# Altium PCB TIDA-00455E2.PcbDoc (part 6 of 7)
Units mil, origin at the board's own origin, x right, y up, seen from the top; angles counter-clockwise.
Board outline 6693 x 6693.1 mil, 8 copper layers (Layer 1 - Top Layer, Layer 2 - GND, Layer 3 - Sensitive, Layer 4 - GND, Layer 5 - PWR, Layer 6 - Signal, Layer 7 - GND, Layer 8 - Bottom Layer), stack 63.122 mil thick; 537 components, 407 nets, 1686 pads, 1249 vias.
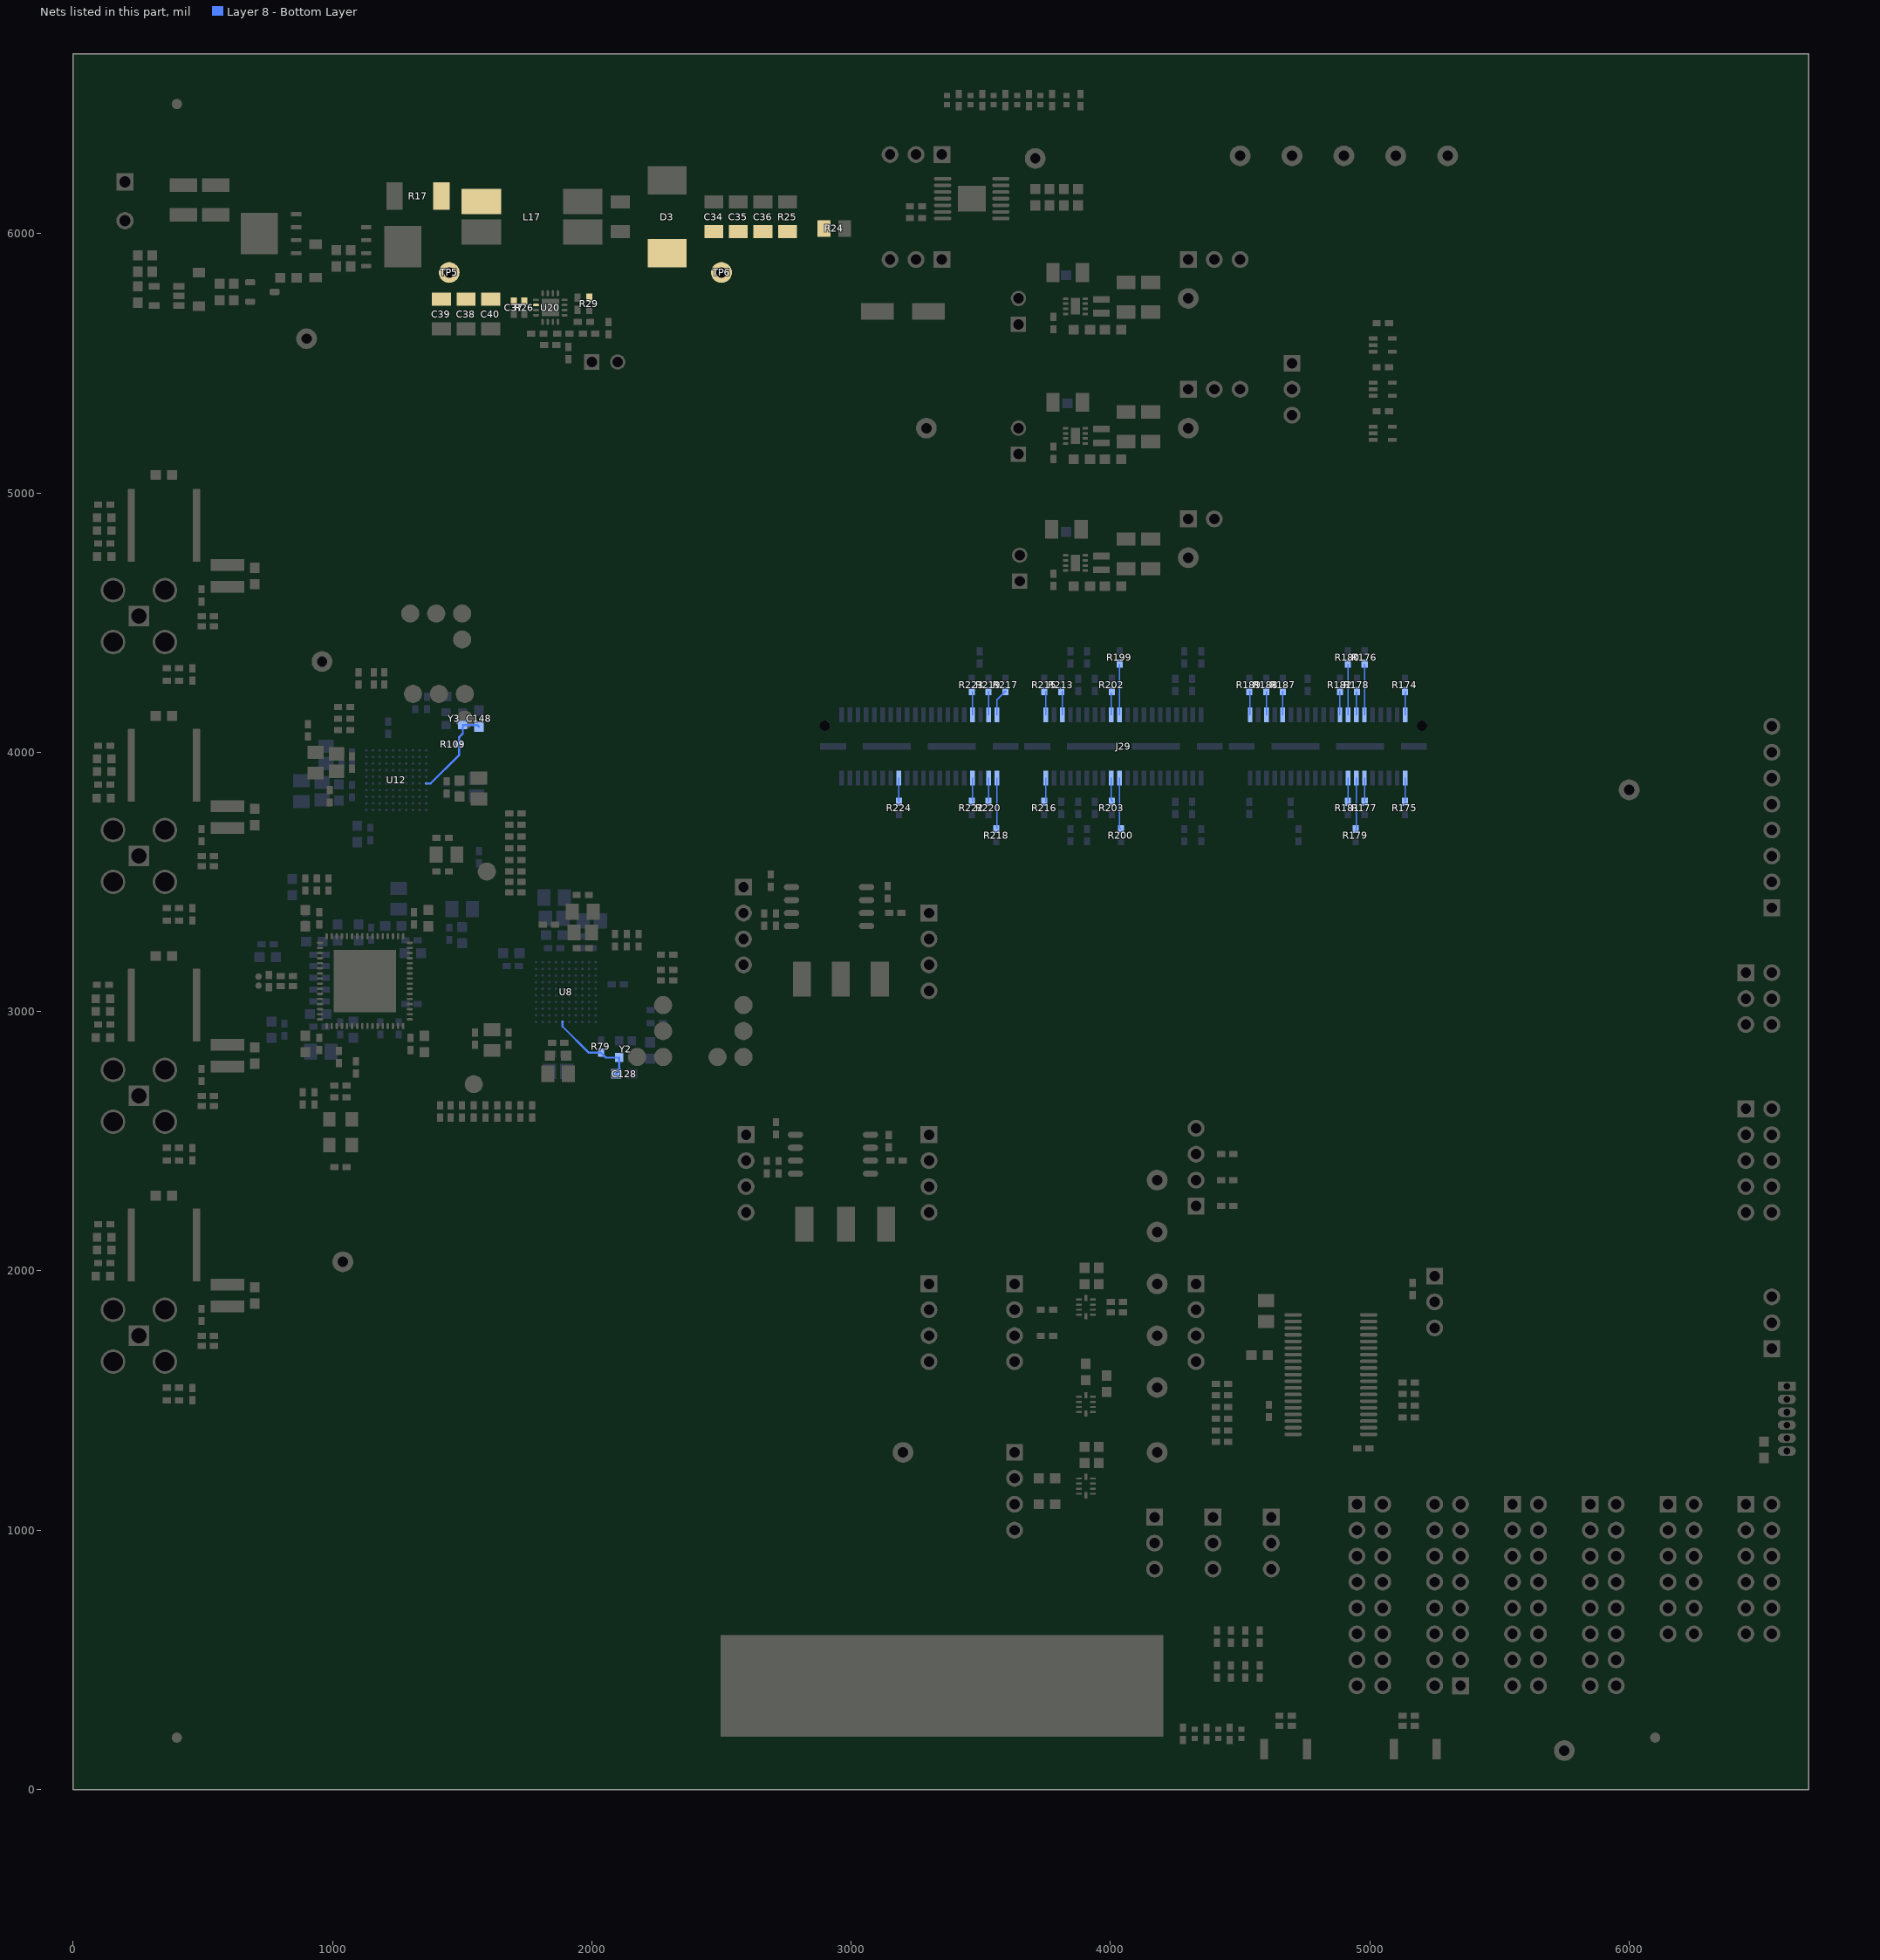
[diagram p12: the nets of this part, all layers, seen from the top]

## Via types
v1: diameter 20, hole 10, Layer 1 - Top Layer to Layer 8 - Bottom Layer, tented both sides, 1063 vias
v2: diameter 12, hole 6, Layer 1 - Top Layer to Layer 8 - Bottom Layer, tented bottom, 140 vias
v3: diameter 19.68, hole 7.87, Layer 1 - Top Layer to Layer 8 - Bottom Layer, 38 vias
v4: diameter 19.68, hole 7.87, Layer 1 - Top Layer to Layer 8 - Bottom Layer, tented top, 4 vias
v5: diameter 15.75, hole 7.87, Layer 1 - Top Layer to Layer 8 - Bottom Layer, 4 vias

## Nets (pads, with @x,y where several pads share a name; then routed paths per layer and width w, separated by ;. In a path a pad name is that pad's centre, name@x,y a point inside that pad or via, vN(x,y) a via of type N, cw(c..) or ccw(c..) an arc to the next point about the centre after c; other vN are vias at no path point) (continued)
VIN1A_HSYNC_0: J29.1 R174.2 | length 90.8
  Layer 8 - Bottom Layer w5: J29.1@5136.8,4143.8 R174.2@5136.8,4234.58
VIN1A_VSYNC_0: J29.2 R175.1 | length 93
  Layer 8 - Bottom Layer w5: R175.1@5135,3808.62 5136.8,3810.42 J29.2@5136.8,3900.89
VIN1B_CLK1: J29.75 R213.2 | length 92.6
  Layer 8 - Bottom Layer w5: J29.75@3813.97,4143.8 R213.2@3813.97,4236.38
VIN2A_CLK: J29.61 R199.2 | length 197
  Layer 8 - Bottom Layer w5: J29.61@4034.44,4143.8 R199.2@4034.44,4340.82
VIN2A_D00: J29.79 R215.2 | length 92.6
  Layer 8 - Bottom Layer w5: J29.79@3750.97,4143.8 R215.2@3750.97,4236.38
VIN2A_D01: J29.80 R216.1 | length 91.3
  Layer 8 - Bottom Layer w5: R216.1@3750.97,3809.6 J29.80@3750.97,3900.89
VIN2A_D02: J29.81 R217.2 | length 114.2
  Layer 8 - Bottom Layer w5: J29.81@3562,4143.8 3562,4202 R217.2@3595.69,4235.69 ; R217.2@3590,4233 3590,4236.38 R217.2@3595,4236.38
VIN2A_D03: J29.82 R218.1 | length 195.3
  Layer 8 - Bottom Layer w5: R218.1@3562,3705.62 J29.82@3562,3900.89
VIN2A_D04: J29.83 R219.2 | length 92.6
  Layer 8 - Bottom Layer w5: J29.83@3530.5,4143.8 R219.2@3530.5,4236.38
VIN2A_D05: J29.84 R220.1 | length 91.8
  Layer 8 - Bottom Layer w5: R220.1@3530.5,3809.12 J29.84@3530.5,3900.89
VIN2A_D06: J29.87 R223.2 | length 90.1
  Layer 8 - Bottom Layer w5: J29.87@3467.51,4143.8 R223.2@3467.51,4233.89
VIN2A_D07: J29.88 R222.1 | length 89.8
  Layer 8 - Bottom Layer w5: R222.1@3467.51,3811.13 J29.88@3467.51,3900.89
VIN2A_DE0: J29.63 R202.2 | length 85.5
  Layer 8 - Bottom Layer w5: J29.63@4002.94,4143.8 R202.2@4002.94,4229.32
VIN2A_HSYNC_0: J29.62 R200.1 | length 199.6
  Layer 8 - Bottom Layer w5: J29.62@4034.44,3900.89 4034.44,3709.18 R200.1@4040,3703.62
VIN2A_VSYNC_0: J29.64 R203.1 | length 93.8
  Layer 8 - Bottom Layer w5: J29.64@4002.94,3900.89 4002.94,3817.06 R203.1@4010,3810
VIN6A_CLK: J29.106 R224.1 | length 92.3
  Layer 8 - Bottom Layer w5: R224.1@3184.04,3808.62 J29.106@3184.04,3900.89
VIN6A_D00: J29.13 R178.2 | length 90.4
  Layer 8 - Bottom Layer w5: J29.13@4947.82,4143.8 R178.2@4947.82,4234.2
VIN6A_D01: J29.14 R179.1 | length 198.4
  Layer 8 - Bottom Layer w5: R179.1@4945,3703.62 4947.82,3706.45 J29.14@4947.82,3900.89
VIN6A_D02: J29.15 R180.2 | length 196.2
  Layer 8 - Bottom Layer w5: J29.15@4916.33,4143.8 R180.2@4916.33,4340.05
VIN6A_D03: J29.16 R181.1 | length 92.8
  Layer 8 - Bottom Layer w5: R181.1@4915,3808.62 4916.33,3809.95 J29.16@4916.33,3900.89
VIN6A_D04: J29.35 R188.2 | length 91.2
  Layer 8 - Bottom Layer w5: J29.35@4601.37,4143.8 R188.2@4601.37,4235.01
VIN6A_D05: J29.39 R189.1 | length 94
  Layer 8 - Bottom Layer w5: R189.1@4535,4236.38 4538.38,4233 J29.39@4538.38,4143.8
VIN6A_D06: J29.31 R187.2 | length 92.6
  Layer 8 - Bottom Layer w5: J29.31@4664.36,4143.8 R187.2@4664.36,4236.38
VIN6A_D07: J29.17 R182.2 | length 92.6
  Layer 8 - Bottom Layer w5: J29.17@4884.83,4143.8 4884.83,4236.21 R182.2@4885,4236.38
VIN6A_HSYNC_0: J29.11 R176.2 | length 196.9
  Layer 8 - Bottom Layer w5: J29.11@4979.32,4143.8 R176.2@4979.32,4340.7
VIN6A_VSYNC_0: J29.12 R177.1 | length 92.5
  Layer 8 - Bottom Layer w5: J29.12@4979.32,3900.89 4979.32,3809.3 R177.1@4980,3808.62
VIN_PROTECT: C37.1 C38.1 C39.1 C40.1 L17.1 R17.2 R26.1 TP5.1 U20.2
VOUT: C34.1 C35.1 C36.1 D3.1 R24.1 R25.2 R29.1 TP6.1
XTAL_OUT_OV1: C128.1 R79.2 U8.F1 Y2.3 | length 352.5
  Layer 8 - Bottom Layer w8: U8.F1@1887.2,2959.84 1887.2,2942.8 1988.62,2841.38 R79.2@2035,2841.38 2053.86,2822.52 Y2.3@2105.39,2822.52 2105.39,2771.89 C128.1@2093.5,2760
XTAL_OUT_OV2: C148.1 R109.2 U12.F1 Y3.3 | length 359.5
  Layer 8 - Bottom Layer w8: U12.F1@1361.4,3879.7 1378.44,3879.7 1488.62,3989.88 R109.2@1488.62,4030 1488.62,4058.62 1502.48,4072.48 Y3.3@1502.48,4105.39 1558.11,4105.39 C148.1@1565,4098.5
pads on no net: FID1.1 FID2.1 FID3.1 FID4.1 FID5.1 FID6.1 J23.1 J23.6 J25.4 J25.6 J29.3 J29.4 J29.5 J29.6 J29.7 J29.8 J29.9 J29.10 J29.18 J29.19 J29.20 J29.21 J29.22 J29.23 J29.24 J29.29 J29.33 J29.36 J29.37 J29.38 J29.86 J29.99 J29.100 J29.101 J29.102 J29.103 J29.104 J29.105 J29.107 J29.108 J29.109 J29.110 J29.111 J29.112 J29.113 J29.114 J29.117 J29.118 J29.119 J29.120 J29.MH1 J29.MH2 J32.2 Logo1.0 R52.2 U2.1 U2.2 U4.1 U4.4 U4.11 U8.B7 U8.B8 U8.B10 U8.C7 U8.E7 U8.F3 U8.F7 U8.H2 U8.J9 U8.J10 U8.K6 U12.B7 U12.B8 U12.B10 U12.C7 U12.E7 U12.F3 U12.F7 U12.H2 U12.J9 U12.J10 U12.K6 U18.1 U18.2 U19.1 U19.2

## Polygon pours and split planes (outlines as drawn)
GND on Layer 2 - GND "Layer 2 - GND- GND" (solid, remove dead copper, pour order 6): 20,20 6670,20 6670,6670 20,6670
GND on Layer 7 - GND "Layer 5 - GND- GND" (solid, remove dead copper, pour order 7): 20,20 6670,20 6670,6670 20,6670
1V8 on Layer 5 - PWR "Layer 3 - PWR- 1V8" (solid, remove dead copper, pour order 9): 4440,5400 4440,5220 4360,5140 4140,4920 2010,4920 1960,4870 1960,4580 1880,4500 900,4500 800,4400 800,4040 1110,3730 1250,3730 1300,3730 1410,3620 1410,3540 1460,3490 1550,3490 1636,3576 1636,3666 1605,3697 1605,3840 1670,3840 1690,3820 1690,3500 1720,3470 1780,3470 1785,3465 1785,3415 1780,3410 1745,3410 1730,3395 1730,3300 1730,3025 1660,2955 1380,2955 1345,2920 1345,2725 1380,2690 1660,2690 1680,2710 1730,2710 1850,2710 1850,2630 1810,2590 1355,2590 1320,2555 1320,2400 1320,2170 1290,2140 660,2140 470,2330 470,5070 850,5450 3690,5450 3840,5600 4360,5600 4440,5520
3V3 on Layer 5 - PWR "Layer 3 - PWR- 3V3" (solid, remove dead copper, pour order 10): 4360,5950 4340,5970 3510,5970 3462.5,5970 3445.62,5970 3310.62,6105 3220,6105 3205.62,6119.37 3205.63,6150.63 3220,6165 3340,6165 3470,6035 3955,6035 4000,6080 4450,6080 6225,6080 6370,5935 6402.5,5902.5 6402.5,3347.5 6370,3315 6370,1670 6490,1550 6490,1245 6370,1125 6370,270 1530,270 1425,375 1425,1615 1465,1655 2150,1655 2465,1970 2465,2545 2500,2580 2590,2670 4880,2670 5010,2800 5010,3530 5060,3580 5510,3580 5670,3740 5670,4870 5490,5050 5370,5050 5300,4980 5300,4790 5480,4610 5480,3850 5400,3770 4920,3770 4810,3660 4810,2900 4750,2840 2490,2840 2300,2650 2300,2200 2240,2140 1390,2140 1360,2170 1360,2530 1390,2560 1465,2560 1474,2551 1474,2536 1486,2524 1564,2524 1575,2535 1575,2550 1585,2560 1645,2560 1654,2551 1654,2536 1666,2524 1784,2524 1820,2560 1880,2620 1880,2760 1829.01,2810.99 1746,2811 1725,2790 1590,2790 1559,2821 1464,2821 1425,2860 1410,2875 1395,2875 1380,2890 1380,2910 1395,2925 1515,2925 1675,2925 1680,2930 1690,2940 1935,2940 1960,2915 2035,2915 2145,3025 2200,3025 2240,3065 2240,3120 2240,3350 2110,3480 1810,3480 1800,3490 1740,3490 1720,3510 1720,3830 1680,3870 1610,3870 1600,3870 1595,3870 1535,3810 1510,3785 1510,3755 1569,3696 1569,3609 1540,3580 1514,3554 1514,3534 1504,3524 1486,3524 1450,3560 1450,3640 1380,3710 1380,3940 1400,3960 1400,4035 1380,4055 1380,4190 1310,4260 1000,4260 960,4220 960,4130 940,4110 870,4110 850,4130 850,4380 930,4460 1900,4460 2010,4570 4370,4570 4570,4770 4570,5520 4360,5730
GND on Layer 4 - GND "Layer 4 - GND- GND" (solid, remove dead copper, pour order 8): 20,20 6670,20 6670,6670 20,6670

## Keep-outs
Keep-Out Layer:
  text ".Layer_Name" at 577,-858.49 h60

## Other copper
Layer 1 - Top Layer:
  region net 3V3: 4395,460 4590,460 4590,585 4395,585
  region net GND: 6640,125 6290,125 6290,425 6640,425
  region net GND: 1915,50 1915,400 2215,400 2215,50
  region net GND: 50,1225 400,1225 400,925 50,925
  region net GND: 5030,5247 5043,5260 5043,5370 5030,5383 4963,5383 4935,5355 4935,5275 4963,5247
  region net GND: 5030,5417 5043,5430 5043,5540 5030,5553 4963,5553 4935,5525 4935,5445 4963,5417
  region net NetJ6_2: 3270,6335 3290,6315 3290,6265 3310,6245 3382,6245 3390,6237 3390,6156 3382,6148 3317,6148 3252,6148 3210,6190 3210,6315 3230,6335
  region net LOCAL_3V3: 3892,5715 4000,5715 4030,5745 4200,5745 4245,5790 4245,5930 4255,5940 4335,5940 4355,5920 4355,5695 4270,5610 4020,5610 4020,5650 3995,5675 3935,5675 3925,5685 3925,5695 3915,5705 3892,5705
  region net GND: 4195,5785 4195,5870 4175,5890 3815,5890 3815,5744 3843,5744 3848,5739 3848,5700 3844,5696 3817,5696 3805,5684 3805,5656 3796,5647 3768,5647 3768,5582 3780,5570 3871,5570 3883,5582 3883,5793 3900,5810 3930,5810 3955,5785
  region net LOCAL_1V8: 3892,5215 4000,5215 4030,5245 4200,5245 4245,5290 4245,5420 4265,5440 4335,5440 4355,5420 4355,5195 4270,5110 4020,5110 4020,5150 3995,5175 3935,5175 3925,5185 3925,5195 3915,5205 3892,5205
  region net GND: 4195,5285 4195,5370 4175,5390 3815,5390 3815,5244 3843,5244 3848,5239 3848,5200 3844,5196 3817,5196 3805,5184 3805,5156 3796,5147 3768,5147 3768,5082 3780,5070 3871,5070 3883,5082 3883,5293 3900,5310 3930,5310 3955,5285
  region net GND: 4195,4795 4195,4880 4175,4900 3815,4900 3815,4754 3843,4754 3848,4749 3848,4710 3844,4706 3817,4706 3805,4694 3805,4666 3796,4657 3768,4657 3768,4592 3780,4580 3871,4580 3883,4592 3883,4803 3900,4820 3930,4820 3955,4795
  region net LOCAL_1V1: 3892,4725 4000,4725 4030,4755 4200,4755 4245,4800 4245,4930 4265,4950 4335,4950 4355,4930 4355,4705 4270,4620 4020,4620 4020,4660 3995,4685 3935,4685 3925,4695 3925,4705 3915,4715 3892,4715
  region net 3V3: 1450,3642.5 1536.24,3642.5 1536.24,3572.5 1450,3572.5
  region net GND: 1041.24,4057.5 1053.24,4057.5 1041.24,4069.5 1041.24,4102.5 1041.24,4217.5 986.24,4217.5 976.24,4207.5 976.24,4057.5
  region net GND: 1091.24,3962.5 1091.24,4047.5 1081.24,4057.5 976.24,4057.5 976.24,4042.5 986.24,4032.5 986.24,3962.5
  region net GND: 1421.24,3857.5 1511.24,3857.5 1511.24,3772.5 1431.24,3772.5 1421.24,3782.5
  region net 1V8: 1526.24,3847.5 1631.24,3847.5 1631.24,3787.5 1531.24,3787.5 1526.24,3792.5
  region net GND: 20,20 6670,20 6670,6670 20,6670 20,50 50,50 50,6640 6640,6640 6640,1590 6655,1590 6655,1270 6640,1270 6640,50 20,50
  region net GND: 2065,3280 2065,3268 2077,3280 2110,3280 2225,3280 2225,3335 2215,3345 2065,3345
  region net GND: 1970,3230 2055,3230 2065,3240 2065,3345 2050,3345 2040,3335 1970,3335
  region net NetC1_1: 340,5090 340,4755 320,4735 125,4735 125,4875 195,4875 210,4890 210,5070 230,5090
  region net NetL3_2: 360,5090 665,5090 720,5035 720,4690 425,4690 360,4755
  region net NetL3_1: 480,4610 705,4610 720,4625 720,4670 495,4670 480,4655
  region net NetL5_1: 480,3685 705,3685 720,3700 720,3745 495,3745 480,3730
  region net NetL5_2: 360,4160 665,4160 720,4105 720,3760 425,3760 360,3825
  region net NetC5_1: 340,4160 340,3825 320,3805 125,3805 125,3945 195,3945 210,3960 210,4140 230,4160
  region net NetL11_1: 480,2760 705,2760 720,2775 720,2820 495,2820 480,2805
  region net NetL11_2: 360,3240 665,3240 680,3225 680,3055 720,3015 720,2840 690,2840 425,2840 360,2905
  region net NetC15_1: 340,3235 340,2900 320,2880 125,2880 125,3020 195,3020 210,3035 210,3215 230,3235
  region net NetL13_1: 480,1835 705,1835 720,1850 720,1895 495,1895 480,1880
  region net NetL13_2: 360,2315 665,2315 720,2260 720,1915 425,1915 360,1980
  region net NetC19_1: 340,2315 340,1980 320,1960 125,1960 125,2100 195,2100 210,2115 210,2295 230,2315
  region net 3V3: 1650,2875 1650,2795 1580,2795 1580,2875
  region net 1V8: 1025,2385 945,2385 925,2405 925,2515 1025,2515
  region net GND: 1050,2555 1130,2555 1130,2615 1050,2615
  region net NetC30_2: 160,6090 160,5915 180,5895 780,5895 800,5915 800,6090 780,6110 180,6110
  region net NetR21_1: 230,5875 230,5775 330,5775 340,5785 340,5805 330,5815 280,5815 270,5825 270,5875
  region net NetC32_1: 285,5835 290,5830 340,5830 390,5780 690,5780 710,5800 710,5855 690,5875 285,5875
  region net NetM1_3: 760,5760 750,5770 750,5845 760,5855 815,5855 825,5845 825,5770 815,5760
  region net NetC29_2: 850,5800 840,5810 840,5885 850,5895 1145,5895 1155,5885 1155,5810 1145,5800
  region net NetC29_1: 840,5915 1150,5915 1150,6035 840,6035
  region net GND: 620,6150 160,6150 130,6120 130,5900 155,5875 210,5875 210,5770 225,5755 340,5755 360,5735 360,5710 380,5690 435,5690 455,5710 455,5745 475,5765 720,5765 740,5745 740,5675 720,5655 120,5655 50,5585 50,5725 50,6170 50,6350 140,6260 600,6260 620,6240
  region net NetQ2_5: 1210,5840 1190,5860 1190,6185 1205,6200 1350,6200 1365,6185 1365,5840
  region net VIN_PROTECT: 1375,6185 1390,6200 1635,6200 1650,6185 1650,6075 1495,6075 1475,6055 1475,5955 1495,5935 1735,5935 1755,5915 1755,5745 1770,5730 1797,5730 1797,5720 1375,5720
  region net NetC33_2: 1797,5739 1776,5739 1770,5745 1770,6035 1790,6055 2130,6055 2150,6035 2150,5850 2130,5830 1850,5830 1835,5815 1835,5758 1804,5758 1797,5751
  region net NetC33_1: 1877.5,6075 1857.5,6095 1857.5,6240 1877.5,6260 2362.5,6260 2362.5,6095 2342.5,6075
  region net VOUT: 1975,5735 1975,5790 1995,5810 2140,5810 2175,5845 2175,5970 2175,6035 2195,6055 2920,6055 2920,5755 2900,5735
  region net GND: 1807,5748 1841,5748 1845,5752 1845,5805 1855,5815 1945,5815 1960,5800 1960,5735 1930,5735 1920,5725 1920,5700 1880,5700 1865,5685 1835,5685 1835,5535 1825,5525 1760,5525 1725,5525 1687.5,5562.5 1710,5585 1710,5605 1730,5585 1785,5585 1795,5595 1795,5640 1805,5650 1805,5670 1807,5672
  region net GND: 1495,5955 1720,5955 1720,6055 1495,6055
  region net GND: 1715,5710 1715,5580 1695,5560 1395,5560 1375,5580 1375,5710
  region net GND: 2430,6075 2410,6095 2410,6175 2430,6195 2790,6195 2810,6175 2810,6095 2790,6075
  region net V_CAM: 3540,6150 3895,6150 3895,6320 3875,6340 3560,6340 3540,6320
  region net V_MAIN: 2950,5880 2970,5860 3165,5860 3185,5880 3185,6320 3165,6340 2970,6340 2950,6320
  region net NetC44_1: 3230,5935 3210,5915 3210,4745 3230,4725 3790,4725 3800,4735 3838,4735 3838,4745 3810,4745 3800,4755 3800,4900 3710,4900 3690,4920 3690,5075 3670,5095 3615,5095 3595,5115 3595,5200 3615,5220 3795,5220 3800,5225 3838,5225 3838,5235 3810,5235 3805,5240 3805,5390 3710,5390 3690,5410 3690,5575 3670,5595 3615,5595 3595,5615 3595,5700 3615,5720 3795,5720 3800,5725 3838,5725 3838,5735 3810,5735 3805,5740 3805,5775 3805,5845 3805,5890 3465,5890 3420,5845 3310,5845 3290,5865 3290,5915 3270,5935
  region net NetL18_1: 3892,5725 3990,5725 4000,5735 4000,5760 3930,5760 3925,5755 3925,5745 3915,5735 3892,5735
  region net NetL19_1: 3892,5225 3990,5225 4000,5235 4000,5260 3930,5260 3925,5255 3925,5245 3915,5235 3892,5235
  region net NetL20_1: 3892,4735 3990,4735 4000,4745 4000,4770 3930,4770 3925,4765 3925,4755 3915,4745 3892,4745
  region net GND: 3165,5650 3150,5635 3050,5635 3035,5650 3035,5750 3050,5765 3150,5765 3165,5750
  region net GND: 4775,110 4705,110 4705,200 4775,200
  region net GND: 5075,110 5145,110 5145,200 5075,200
  region net GND: 3899,1147 3913,1147 3915,1145 3965,1145 3975,1135 3975,1105 3965,1095 3909,1095 3899,1105
  region net GND: 3899,1462 3913,1462 3915,1460 3965,1460 3975,1450 3975,1420 3965,1410 3909,1410 3899,1420
  region net GND: 3899,1837 3913,1837 3915,1835 3965,1835 3975,1825 3975,1795 3965,1785 3909,1785 3899,1795
  region net GND: 1865,2900 1865,2810 1780,2810 1780,2890 1790,2900
  region net 1V8: 1855,2795 1855,2690 1795,2690 1795,2790 1800,2795
  region net GND: 50,5575 400,5575 400,5275 50,5275
  region net GND: 5400,6290 5400,6640 5700,6640 5700,6290
  region net GND: 380,2410 380,2505 410,2535 410,2650 335,2650 300,2615 205,2615 190,2630 190,2720 205,2735 300,2735 335,2700 410,2700 410,2815 375,2850 50,2850 50,2410
  region net GND: 380,3335 380,3430 410,3460 410,3575 335,3575 300,3540 205,3540 190,3555 190,3645 205,3660 300,3660 335,3625 410,3625 410,3740 375,3775 50,3775 50,3335
  region net GND: 380,1485 380,1580 410,1610 410,1725 335,1725 300,1690 205,1690 190,1705 190,1795 205,1810 300,1810 335,1775 410,1775 410,1890 375,1925 50,1925 50,1485
  region net GND: 380,4260 380,4355 410,4385 410,4500 335,4500 300,4465 205,4465 190,4480 190,4570 205,4585 300,4585 335,4550 410,4550 410,4665 375,4700 50,4700 50,4260
  text ".Layer_Name" at 577,-858.49 h60
Layer 2 - GND:
  pour cut-out: 1827.5,3226.24 1827.5,3156.24 1792.5,3156.24 1792.5,3176.24 1747.5,3176.24 1747.5,3101.24 1775.5,3101.24 1775.5,2951.24 1847.5,2951.24 1847.5,2891.24 1902.5,2891.24 1902.5,2951.24 1952.5,2951.24 1952.5,2925.24 2024.5,2925.24 2024.5,2950.24 2052.5,2950.24 2052.5,3096.24 2035.76,3096.24 2024.5,3107.5 2024.5,3132 2024.5,3201.24 1897.5,3201.24 1897.5,3226.24
  pour cut-out: 1095,3820 1165,3820 1165,3785 1145,3785 1145,3740 1220,3740 1220,3768 1370,3768 1370,3840 1430,3840 1430,3895 1370,3895 1370,3945 1396,3945 1396,4017 1371,4017 1371,4045 1240,4045 1212,4017 1195,4017 1120,4017 1120,3890 1095,3890
  region net GND: 2025,3120 1976,3120 1961,3105 1950,3105 1942,3113 1942,3130 1945,3133 2025,3133
  pour cut-out: 1040,4440 1040,4400 1070,4370 1070,4340 1090,4320 1257,4320 1290,4353 1290,4410 1260,4440
  pour cut-out: 2325,3230 2345,3250 2420,3250 2440,3230 2440,3180 2450,3170 2450,3135 2495,3090 2495,3070 2475,3050 2455,3050 2415,3090 2345,3090 2325,3110
  pour cut-out: 4900,345 5100,345 5100,1150 4900,1150
  pour cut-out: 5200,345 5400,345 5400,1150 5200,1150
  pour cut-out: 5500,345 5700,345 5700,1150 5500,1150
  pour cut-out: 6100,550 6300,550 6300,1150 6100,1150
  pour cut-out: 6400,550 6600,550 6600,1150 6400,1150
  pour cut-out: 5900,1150 6000,1150 6000,350 5900,350
  pour cut-out: 6500,1645 6600,1645 6600,1950 6500,1950
  pour cut-out: 6400,2175 6500,2175 6500,2275 6600,2275 6600,2575 6500,2575 6500,2675 6400,2675
  pour cut-out: 6400,2900 6600,2900 6600,3200 6400,3200
  pour cut-out: 6500,3350 6600,3350 6600,4050 6500,4050
  pour cut-out: 4380,2505 4280,2505 4280,2200 4380,2200
  pour cut-out: 4380,2005 4280,2005 4280,1700 4380,1700
  pour cut-out: 3680,2005 3580,2005 3580,1700 3680,1700
  pour cut-out: 3350,2005 3250,2005 3250,1700 3350,1700
  pour cut-out: 3350,2580 3250,2580 3250,2275 3350,2275
  pour cut-out: 2645,2580 2545,2580 2545,2275 2645,2275
  pour cut-out: 2635,3535 2535,3535 2535,3230 2635,3230
  pour cut-out: 3350,3435 3250,3435 3250,3130 3350,3130
  pour cut-out: 3405,6255 3405,6355 3100,6355 3100,6255
  pour cut-out: 3405,5850 3405,5950 3100,5950 3100,5850
  pour cut-out: 4555,5850 4555,5950 4250,5950 4250,5850
  pour cut-out: 4555,5350 4555,5450 4250,5450 4250,5350
  pour cut-out: 4750,5555 4650,5555 4650,5250 4750,5250
  pour cut-out: 3680,1355 3580,1355 3580,1050 3680,1050
  pour cut-out: 1950,5455 2150,5455 2150,5555 1950,5555
  pour cut-out: 3695,5600 3695,5800 3595,5800 3595,5600
  pour cut-out: 3695,5100 3695,5300 3595,5300 3595,5100
  pour cut-out: 3700,4610 3700,4810 3600,4810 3600,4610
  pour cut-out: 4250,4850 4450,4850 4450,4950 4250,4950
  pour cut-out: 5200,2030 5200,1830 5300,1830 5300,2030
  pour cut-out: 4570,1100 4570,900 4670,900 4670,1100
  pour cut-out: 4345,1100 4345,900 4445,900 4445,1100
  pour cut-out: 4120,1100 4120,900 4220,900 4220,1100
  region net GND: 1201.24,4017.5 1201.24,3968.5 1216.24,3953.5 1216.24,3942.5 1208.24,3934.5 1191.24,3934.5 1188.24,3937.5 1188.24,4017.5
  text ".Layer_Name" at 577,-858.49 h60
Layer 5 - PWR:
  pour cut-out: 3350,3335 3250,3335 3250,3030 3350,3030
  pour cut-out: 2635,3435 2535,3435 2535,3130 2635,3130
  region net 3V3: 6402.5,3347.5 6572.5,3347.5 6590,3365 6590,3435 6575,3450 6450,3450 6395,3505 6395,3355
  pour cut-out: 4900,345 5100,345 5100,1150 4900,1150
  pour cut-out: 5200,345 5400,345 5400,1150 5200,1150
  pour cut-out: 5500,345 5700,345 5700,1150 5500,1150
  pour cut-out: 5800,345 6000,345 6000,1150 5800,1150
  pour cut-out: 6100,545 6300,545 6300,1150 6100,1150
  pour cut-out: 4120,1000 4120,800 4220,800 4220,1000
  pour cut-out: 4345,1000 4345,800 4445,800 4445,1000
  pour cut-out: 4570,1000 4570,800 4670,800 4670,1000
  pour cut-out: 5200,1930 5200,1730 5300,1730 5300,1930
  pour cut-out: 3680,1255 3580,1255 3580,950 3680,950
  pour cut-out: 3350,1905 3250,1905 3250,1600 3350,1600
  pour cut-out: 3680,1905 3580,1905 3580,1600 3680,1600
  pour cut-out: 4380,1905 4280,1905 4280,1600 4380,1600
  pour cut-out: 3350,2480 3250,2480 3250,2175 3350,2175
  pour cut-out: 2645,2480 2545,2480 2545,2175 2645,2175
  pour cut-out: 4750,5555 4650,5555 4650,5250 4750,5250
  pour cut-out: 4380,2605 4280,2605 4280,2200 4380,2200
  text ".Layer_Name" at 577,-858.49 h60
Layer 6 - Signal:
  text ".Layer_Name" at 577,-858.49 h60
Layer 7 - GND:
  pour cut-out: 1095,3820 1165,3820 1165,3785 1145,3785 1145,3740 1220,3740 1220,3768 1370,3768 1370,3840 1430,3840 1430,3895 1370,3895 1370,3945 1396,3945 1396,4017 1371,4017 1371,4045 1240,4045 1212,4017 1195,4017 1120,4017 1120,3890 1095,3890
  pour cut-out: 1827.5,3226.24 1827.5,3156.24 1792.5,3156.24 1792.5,3176.24 1747.5,3176.24 1747.5,3101.24 1775.5,3101.24 1775.5,2951.24 1847.5,2951.24 1847.5,2891.24 1902.5,2891.24 1902.5,2951.24 1952.5,2951.24 1952.5,2925.24 2024.5,2925.24 2024.5,2950.24 2052.5,2950.24 2052.5,3096.24 2035.76,3096.24 2024.5,3107.5 2024.5,3132 2024.5,3201.24 1897.5,3201.24 1897.5,3226.24
  region net GND: 2025,3120 1976,3120 1961,3105 1950,3105 1942,3113 1942,3130 1945,3133 2025,3133
  pour cut-out: 1040,4440 1040,4400 1070,4370 1070,4340 1090,4320 1260,4320 1290,4350 1290,4410 1260,4440
  pour cut-out: 2325,3230 2345,3250 2420,3250 2440,3230 2440,3180 2450,3170 2450,3135 2495,3090 2495,3070 2475,3050 2455,3050 2415,3090 2345,3090 2325,3110
  pour cut-out: 5900,1150 6000,1150 6000,350 5900,350
  pour cut-out: 6400,550 6600,550 6600,1150 6400,1150
  pour cut-out: 6100,550 6300,550 6300,1150 6100,1150
  pour cut-out: 5500,345 5700,345 5700,1150 5500,1150
  pour cut-out: 5200,345 5400,345 5400,1150 5200,1150
  pour cut-out: 4900,345 5100,345 5100,1150 4900,1150
  pour cut-out: 6500,3350 6600,3350 6600,4050 6500,4050
  pour cut-out: 6400,2900 6600,2900 6600,3200 6400,3200
  pour cut-out: 6400,2175 6500,2175 6500,2275 6600,2275 6600,2575 6500,2575 6500,2675 6400,2675
  pour cut-out: 6500,1645 6600,1645 6600,1950 6500,1950
  pour cut-out: 4280,2195 4380,2195 4380,2500 4280,2500
  pour cut-out: 4280,1695 4380,1695 4380,2000 4280,2000
  pour cut-out: 3580,1695 3680,1695 3680,2000 3580,2000
  pour cut-out: 3250,1695 3350,1695 3350,2000 3250,2000
  pour cut-out: 3580,1045 3680,1045 3680,1350 3580,1350
  pour cut-out: 3250,2270 3350,2270 3350,2575 3250,2575
  pour cut-out: 2545,2270 2645,2270 2645,2575 2545,2575
  pour cut-out: 2535,3225 2635,3225 2635,3530 2535,3530
  pour cut-out: 3250,3125 3350,3125 3350,3430 3250,3430
  pour cut-out: 4650,5245 4750,5245 4750,5550 4650,5550
  pour cut-out: 3095,6355 3095,6255 3400,6255 3400,6355
  pour cut-out: 3095,5950 3095,5850 3400,5850 3400,5950
  pour cut-out: 4245,5950 4245,5850 4550,5850 4550,5950
  pour cut-out: 4245,5450 4245,5350 4550,5350 4550,5450
  pour cut-out: 3595,5800 3595,5600 3695,5600 3695,5800
  pour cut-out: 3595,5300 3595,5100 3695,5100 3695,5300
  pour cut-out: 3600,4810 3600,4610 3700,4610 3700,4810
  pour cut-out: 1950,5455 2150,5455 2150,5555 1950,5555
  pour cut-out: 4250,4850 4450,4850 4450,4950 4250,4950
  pour cut-out: 5200,2030 5200,1830 5300,1830 5300,2030
  pour cut-out: 4570,1100 4570,900 4670,900 4670,1100
  pour cut-out: 4345,1100 4345,900 4445,900 4445,1100
  pour cut-out: 4120,1100 4120,900 4220,900 4220,1100
  region net GND: 1201.24,4017.5 1201.24,3968.5 1216.24,3953.5 1216.24,3942.5 1208.24,3934.5 1191.24,3934.5 1188.24,3937.5 1188.24,4017.5
  text ".Layer_Name" at 577,-858.49 h60
Layer 3 - Sensitive:
  text ".Layer_Name" at 577,-858.49 h60
Layer 4 - GND:
  pour cut-out: 1827.5,3226.24 1827.5,3156.24 1792.5,3156.24 1792.5,3176.24 1747.5,3176.24 1747.5,3101.24 1775.5,3101.24 1775.5,2951.24 1847.5,2951.24 1847.5,2891.24 1902.5,2891.24 1902.5,2951.24 1952.5,2951.24 1952.5,2925.24 2024.5,2925.24 2024.5,2950.24 2052.5,2950.24 2052.5,3096.24 2035.76,3096.24 2024.5,3107.5 2024.5,3132 2024.5,3201.24 1897.5,3201.24 1897.5,3226.24
  pour cut-out: 1095,3820 1165,3820 1165,3785 1145,3785 1145,3740 1220,3740 1220,3768 1370,3768 1370,3840 1430,3840 1430,3895 1370,3895 1370,3945 1396,3945 1396,4017 1371,4017 1371,4045 1240,4045 1212,4017 1195,4017 1120,4017 1120,3890 1095,3890
  region net GND: 2025,3120 1976,3120 1961,3105 1950,3105 1942,3113 1942,3130 1945,3133 2025,3133
  pour cut-out: 1040,4440 1040,4400 1070,4370 1070,4340 1090,4320 1263,4320 1290,4347 1290,4410 1260,4440
  pour cut-out: 2325,3230 2345,3250 2420,3250 2440,3230 2440,3180 2450,3170 2450,3135 2495,3090 2495,3070 2475,3050 2455,3050 2415,3090 2345,3090 2325,3110
  pour cut-out: 5900,1150 6000,1150 6000,350 5900,350
  pour cut-out: 6400,550 6600,550 6600,1150 6400,1150
  pour cut-out: 6100,550 6300,550 6300,1150 6100,1150
  pour cut-out: 5500,345 5700,345 5700,1150 5500,1150
  pour cut-out: 5200,345 5400,345 5400,1150 5200,1150
  pour cut-out: 4900,345 5100,345 5100,1150 4900,1150
  pour cut-out: 6500,3350 6600,3350 6600,4050 6500,4050
  pour cut-out: 6400,2900 6600,2900 6600,3200 6400,3200
  pour cut-out: 6400,2175 6500,2175 6500,2275 6600,2275 6600,2575 6500,2575 6500,2675 6400,2675
  pour cut-out: 6500,1645 6600,1645 6600,1950 6500,1950
  pour cut-out: 4380,2005 4280,2005 4280,1700 4380,1700
  pour cut-out: 4380,2505 4280,2505 4280,2200 4380,2200
  pour cut-out: 3680,2005 3580,2005 3580,1700 3680,1700
  pour cut-out: 3350,2005 3250,2005 3250,1700 3350,1700
  pour cut-out: 3680,1355 3580,1355 3580,1050 3680,1050
  pour cut-out: 3350,2580 3250,2580 3250,2275 3350,2275
  pour cut-out: 2645,2580 2545,2580 2545,2275 2645,2275
  pour cut-out: 2635,3535 2535,3535 2535,3230 2635,3230
  pour cut-out: 3350,3435 3250,3435 3250,3130 3350,3130
  pour cut-out: 4750,5555 4650,5555 4650,5250 4750,5250
  pour cut-out: 3095,6355 3095,6255 3400,6255 3400,6355
  pour cut-out: 3095,5950 3095,5850 3400,5850 3400,5950
  pour cut-out: 4245,5950 4245,5850 4550,5850 4550,5950
  pour cut-out: 4245,5450 4245,5350 4550,5350 4550,5450
  pour cut-out: 1950,5455 2150,5455 2150,5555 1950,5555
  pour cut-out: 3595,5800 3595,5600 3695,5600 3695,5800
  pour cut-out: 3595,5300 3595,5100 3695,5100 3695,5300
  pour cut-out: 3600,4810 3600,4610 3700,4610 3700,4810
  pour cut-out: 4250,4850 4450,4850 4450,4950 4250,4950
  pour cut-out: 5200,2030 5200,1830 5300,1830 5300,2030
  pour cut-out: 4570,1100 4570,900 4670,900 4670,1100
  pour cut-out: 4345,1100 4345,900 4445,900 4445,1100
  pour cut-out: 4120,1100 4120,900 4220,900 4220,1100
  region net GND: 1201.24,4017.5 1201.24,3968.5 1216.24,3953.5 1216.24,3942.5 1208.24,3934.5 1191.24,3934.5 1188.24,3937.5 1188.24,4017.5
  text ".Layer_Name" at 577,-858.49 h60
Layer 8 - Bottom Layer:
  region net GND: 6640,125 6290,125 6290,425 6640,425
  region net GND: 1915,50 1915,400 2215,400 2215,50
  region net GND: 50,1225 400,1225 400,925 50,925
  region net GND: 1421.24,3857.5 1421.24,3782.5 1446.24,3757.5 1586.24,3757.5 1586.24,3857.5
  region net 3V3: 1521.24,3867.5 1631.24,3867.5 1631.24,3927.5 1526.24,3927.5 1521.24,3922.5
  region net GND: 1091.24,3842.5 931.24,3842.5 931.24,3752.5 1041.24,3752.5 1091.24,3802.5
  region net 1V8: 846.24,3842.5 846.24,3752.5 916.24,3752.5 916.24,3842.5
  region net GND: 1088.24,3980.5 1088.24,4075.5 1071.24,4092.5 931.24,4092.5 931.24,3997.5 1006.24,3997.5 1019.24,3984.5 1019.24,3980.5
  region net GND: 1988,3233 2083,3233 2100,3250 2100,3390 2005,3390 2005,3315 1992,3302 1988,3302
  region net GND: 1300,3295 1300,2970 1270,2940 1006,2940 994,2928 955,2928 955,3235 940,3250 940,3295
  region net 1V8: 1850,3475 1760,3475 1760,3405 1850,3405
  region net GND: 1850,3230 1850,3390 1760,3390 1760,3280 1810,3230
  region net V_CAM: 3565,6160 3680,6160 3680,6225 3575,6225 3565,6215
  region net 3V3: 1875,2800 1875,2690 1935,2690 1935,2795 1930,2800
  region net GND: 1865,2900 1790,2900 1765,2875 1765,2735 1865,2735
  region net GND: 50,5575 400,5575 400,5275 50,5275
  region net GND: 5400,6290 5400,6640 5700,6640 5700,6290
  region net GND: 2135,2740 2135,2840 2250,2840 2250,2715 2160,2715
  region net GND: 1480,4135 1595,4135 1620,4160 1620,4250 1480,4250
  region net GND: 20,20 6670,20 6670,6670 20,6670 20,50 50,50 50,6640 6640,6640 6640,1590 6655,1590 6655,1270 6640,1270 6640,50 20,50
  region net 1V1: 960,1835 960,1905 905,1905 885,1885 885,1855 905,1835
  text ".Layer_Name" at 577,-858.49 h60

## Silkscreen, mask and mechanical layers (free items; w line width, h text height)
Top Overlay:
  circle w10: c3792.76,4760 r2.24
  circle w10: c3796.76,5250 r2.24
  circle w10: c3797.76,5750 r2.24
  circle w10: c3624.76,6030 r2.24
  circle w10: c1756.76,5777 r2.24
  circle w10: c407.76,5689 r2.24
  circle w10: c982.76,2904 r2.24
  circle w10: c3851.76,1200 r2.24
  circle w10: c3847.76,1514 r2.24
  circle w10: c3842.76,1890 r2.24
  circle w10: c4704,1851 r2.24
  lines w10: 170,3142.5 170,3190 ; 175,2220 175,2267.5 ; 175,4065 175,4125 ; 175,4150 175,4125 ; 175,4995 175,5055 ; 175,5080 175,5055 ; 180,3220 170,3210 170,3190 ; 185,2297.5 175,2287.5 175,2267.5 ; 265,4150 265,4125 175,4125 ; 265,5080 265,5055 175,5055 ; 275,3202.5 262.5,3190 170,3190 ; 280,2280 267.5,2267.5 175,2267.5 ; 1710,5590 1710,5640 ; 1775,5480 1815,5520 ; 3325,6510 3345,6510 ; 3325,6580 3335,6580 3460,6580 3460,6565 ; 3325,6625 3345,6625 3550,6625 3550,6565 ; 3640,6565 3640,6625 3920,6625 3940,6625 ; 3730,6565 3730,6580 3930,6580 3940,6580 ; 3920,6510 3940,6510 ; 4300,4970 4300,5010 ; 4300,5470 4300,5510 ; 4300,5970 4300,6010 ; 4400,4970 4400,5010 ; 4400,5470 4400,5510 ; 4400,5970 4400,6010 ; 4500,5470 4500,5510 ; 4500,5970 4500,6010
  text "V_CAM" at 3145,6605 h50
  text "LOCAL_1V1" at 3955,6605 h50
  text "V_MAIN" at 3145,6550 h50
  text "LOCAL_1V8" at 3955,6550 h50
  text "BATTERY" at 3105,6495 h50
  text "LOCAL_3V3" at 3955,6495 h50
  text "V CAM4" at 4415,6375 h50
  text "V CAM3" at 4615,6375 h50
  text "V CAM2" at 4815,6375 h50
  text "V CAM1" at 5015,6375 h50
  text "GND" at 5250,6375 h50
  text "GND" at 60,6295 h75
  text "V_MAIN" at 2915,6290 h50
  text "EVM_12V" at 3420,6290 h50
  text "VCAM" at 3810,6260 h50
  text "LOCAL_3V3" at 4310,6020 h50 r45
  text "3V3" at 4410,6020 h50 r45
  text "EVM_3V3" at 4500,6020 h50 r45
  text "VIN" at 1395,5925 h50
  text "VIN" at 60,5900 h75
  text "V_MAIN" at 2915,5885 h50
  text "EVM_12V" at 3420,5885 h50
  text "VOUT" at 2440,5710 h50
  text "GND" at 850,5670 h50
  text "LOCAL_1V8" at 4310,5520 h50 r45
  text "1V8" at 4410,5520 h50 r45
  text "EVM_1V8" at 4500,5520 h50 r45
  text "PG_3V3" at 4770,5490 h50
  text "PG_1V8" at 4770,5390 h50
  text "PG_1V1" at 4770,5290 h50
  text "LOCAL_1V1" at 4310,5020 h50 r45
  text "1V1" at 4410,5020 h50 r45
  text "GND" at 910.12,4425.18 h50
  text "Camera 1" at 465,4380 h75
  text "GND" at 5950.12,3930.18 h50
  text "Camera 2" at 465,3455 h75
  text "3V3" at 3387,3368 h50
  text "GND" at 3387,3064 h50
  text "Camera 3" at 465,2530 h75
  text "3V3" at 2430,2505 h50
  text "3V3" at 3380,2505 h50
  text "GND" at 4130,2425 h50
  text "GND" at 2415,2205 h50
  text "GND" at 3380,2205 h50
  text "GND" at 990,2110 h50
  text "3V3" at 5330,1960 h50
  text "3V3" at 3480,1930 h50
  text "3V3" at 4390,1930 h50
  text "MODE UC" at 5330,1860 h50
  text "SCL SOC" at 3370,1830 h50
  text "SCL UC" at 4390,1830 h50
  text "GND" at 5330,1760 h50
  text "SDA SOC" at 3370,1730 h50
  text "SDA UC" at 4390,1730 h50
  text "GND" at 3470,1630 h50
  text "GND" at 4390,1630 h50
  text "Camera 4" at 465,1605 h75
  text "GND" at 6460,1495 h50
  text "TDIO1" at 6430,1440 h50
  text "SBWTCK1" at 6340,1385 h50
  text "GND" at 3150.12,1375.18 h50
  text "3V3" at 3480,1280 h50
  text "SCL EXT" at 3370,1180 h50
  text "GPIO" at 4710,1085 h50
  text "0" at 4840,1085 h50
  text "0" at 5140,1085 h50
  text "0" at 5440,1085 h50
  text "0" at 5740,1085 h50
  text "0" at 6040,1085 h50
  text "0" at 6340,1085 h50
  text "SDA EXT" at 3370,1080 h50
  text "3V3" at 4240,1030 h50
  text "3V3" at 4470,1030 h50
  text "1" at 4840,985 h50
  text "1" at 5140,985 h50
  text "1" at 5440,985 h50
  text "1" at 5740,985 h50
  text "1" at 6040,985 h50
  text "1" at 6340,985 h50
  text "GND" at 3460,980 h50
  text "2" at 4840,885 h50
  text "2" at 5140,885 h50
  text "2" at 5440,885 h50
  text "2" at 5740,885 h50
  text "2" at 6040,885 h50
  text "2" at 6340,885 h50
  text "GND" at 4235,835 h50
  text "GND" at 4460,835 h50
  text "3" at 4840,785 h50
  text "3" at 5140,785 h50
  text "3" at 5440,785 h50
  text "3" at 5740,785 h50
  text "3" at 6040,785 h50
  text "3" at 6340,785 h50
  text "1" at 4160,740 h50
  text "2" at 4385,740 h50
  text "4" at 4610,740 h50
  text "4" at 4840,685 h50
  text "4" at 5140,685 h50
  text "4" at 5440,685 h50
  text "4" at 5740,685 h50
  text "4" at 6040,685 h50
  text "4" at 6340,685 h50
  text "SPARE_UC" at 4280,675 h50
  text "5" at 4840,585 h50
  text "5" at 5140,585 h50
  text "5" at 5440,585 h50
  text "5" at 5740,585 h50
  text "5" at 6040,585 h50
  text "5" at 6340,585 h50
  text "GPIO" at 6150,500 h50
  text "GPIO" at 6450,500 h50
  text "6" at 4840,485 h50
  text "6" at 5140,485 h50
  text "6" at 5440,485 h50
  text "6" at 5740,485 h50
  text "6" at 6040,485 h50
  text "OV1" at 6160,455 h50
  text "OV2" at 6460,455 h50
  text "GPIO" at 4710,385 h50
  text "7" at 4840,385 h50
  text "7" at 5140,385 h50
  text "7" at 5440,385 h50
  text "7" at 5740,385 h50
  text "7" at 6040,385 h50
  text "SPARE_UC" at 4280,325 h50
  text "GPIO" at 4950,300 h50
  text "GPIO" at 5250,300 h50
  text "GPIO" at 5550,300 h50
  text "GPIO" at 5850,300 h50
  text "1" at 4300,275 h50
  text "2" at 4390,275 h50
  text "4" at 4480,275 h50
  text "UC" at 4975,255 h50
  text "UB960" at 5235,255 h50
  text "SOC" at 5560,255 h50
  text "GND" at 5855,255 h50
  text "GND" at 5835.12,120.18 h50
  text "TIDA-00455" at 2625,65 h150
  text "REV. E2" at 3455,65 h150
  text "RESET" at 4610,55 h50
  text "SPARE UC 3" at 5040,55 h50
  text ".Layer_Name" at 577,-858.49 h60
Bottom Overlay:
  lines w10: 735,3010 850,3010 870,2990 ; 745,3310 760,3295 850,3295 ; 3630,4350 3780,4350 ; 3635,3695 3785,3695 ; 3780,4385 3780,4350 ; 3785,3660 3785,3695 ; 3800,4330 3780,4350 ; 3805,3715 3785,3695
  text "K1" at 1125,4043 h50 r270
  text "A1" at 1350,4043 h50 r270
  text "A10" at 1350,3660 h50 r270
  text "K1" at 2100,3180 h50
  text "A10" at 1750,2940 h50
  text "A1" at 2100,2940 h50
  text ".Layer_Name" at 577,-858.49 h60
Top Paste:
  text ".Layer_Name" at 577,-858.49 h60
Bottom Paste:
  text ".Layer_Name" at 577,-858.49 h60
Top Solder:
  region: 6640,125 6290,125 6290,425 6640,425
  region: 1915,50 1915,400 2215,400 2215,50
  region: 50,1225 400,1225 400,925 50,925
  region: 20,20 6670,20 6670,6670 20,6670 20,50 50,50 50,6640 6640,6640 6640,50 20,50
  region: 50,5575 400,5575 400,5275 50,5275
  region: 5400,6290 5400,6640 5700,6640 5700,6290
  text ".Layer_Name" at 577,-858.49 h60
  text ".Layer_Name" at 577,-858.49 h60
Bottom Solder:
  region: 6640,125 6290,125 6290,425 6640,425
  region: 1915,50 1915,400 2215,400 2215,50
  region: 50,1225 400,1225 400,925 50,925
  region: 20,20 6670,20 6670,6670 20,6670 20,50 50,50 50,6640 6640,6640 6640,50 20,50
  region: 50,5575 400,5575 400,5275 50,5275
  region: 5400,6290 5400,6640 5700,6640 5700,6290
  text ".Layer_Name" at 577,-858.49 h60
Drill Guide:
  text ".Layer_Name" at 577,-858.49 h60
M1 Board Outline:
  the board outline again, w10
  text ".Layer_Name" at 577,-858.49 h60
M2 Board Dimensions:
  rectangle: 125,-400 500,-275
  rectangle: 0,-275 125,-150
  lines w7: 0,-275 1000,-275 ; 125,-400 125,-150 ; 250,-400 250,-150 ; 500,-400 500,-150 ; 750,-400 750,-150 ; 0,-400 0,-150 1000,-150 1000,-400 0,-400
  text ".Layer_Name" at 577,-858.49 h60
M3 3D STEP Top:
  text ".Layer_Name" at 577,-858.49 h60
M4 3D STEP Bottom:
  text ".Layer_Name" at 577,-858.49 h60
M5 Assembly Top:
  lines w10: -292,-930.17 6308,-930.17 ; -292,-726.83 6310,-726.83 ; -292,-523.5 -292,-1133.5 3713,-1133.5 6310,-1133.5 6310,-523.5 -291.5,-523.5 -291.5,-1133.5 1284,-1133.5 ; 2173,-1133.5 2173,-523.5 ; 3440,-726.83 3440,-523.5 ; 4280,-726.83 4280,-523.5 ; 4902,-1140 4902,-937.17
  text "COMPONENTS MARKED 'DNP' SHOULD NOT BE POPULATED." at 1153.5,-318.5 h60
  text "ASSEMBLY VARIANT:" at 1153,-434 h60
  text ".VariantName" at 2189,-434 h60
  text "PCB VIEWED FROM TOP SIDE" at -228.5,-655.67 h60
  text "BOARD #:" at 2248,-655.67 h60
  text ".PRJ_Number" at 2793.5,-655.67 h60
  text "REV:" at 3638,-655.67 h60
  text ".PCB_Rev" at 3929.5,-655.67 h60
  text "SVN REV:" at 4476,-655.67 h60
  text ".VersionControl_RevNumber" at 4982,-655.67 h60
  text "PLOT NAME =" at -228.5,-1064.34 h60
  text ".plot_File_Name" at 577,-1064.34 h60
  text "GENERATED    :" at 2250,-1064.34 h60
  text ".Print_Date" at 3119.5,-1064.34 h60
  text ".Print_Time" at 3848.5,-1064.34 h60
  text "TEXAS INSTRUMENTS" at 5113,-1064.34 h60
M6 Assembly Bottom:
  lines w10: -292.5,-727.33 6309.5,-727.33 ; -290.5,-930.67 6309.5,-930.67 ; 1115.5,-1140.5 1115.5,-937.67 ; 1737.5,-727.33 1737.5,-524 ; 2577.5,-727.33 2577.5,-524 ; 3844.5,-1134 3844.5,-524 ; 4733.5,-1134 6309,-1134 6309,-524 -292.5,-524 -292.5,-1134 2304.5,-1134 6309.5,-1134 6309.5,-524
  text "COMPONENTS MARKED 'DNP' SHOULD NOT BE POPULATED." at 6102,-318 h60
  text ".VariantName" at 5058,-434 h60
  text "ASSEMBLY VARIANT:" at 6097,-434 h60
  text ".VersionControl_RevNumber" at 1035.5,-656.17 h60
  text "SVN REV:" at 1541.5,-656.17 h60
  text ".PCB_Rev" at 2088,-656.17 h60
  text "REV:" at 2379.5,-656.17 h60
  text ".PRJ_Number" at 3224,-656.17 h60
  text "BOARD #:" at 3769.5,-656.17 h60
  text "PCB VIEWED FROM BOTTOM SIDE" at 6246,-656.17 h60
  text "TEXAS INSTRUMENTS" at 904.5,-1064.84 h60
  text ".Print_Time" at 2169,-1064.84 h60
  text ".Print_Date" at 2898,-1064.84 h60
  text "GENERATED    :" at 3767.5,-1064.84 h60
  text ".plot_File_Name" at 5440.5,-1064.84 h60
  text "PLOT NAME =" at 6246,-1064.84 h60
M9 Title Sheet:
  drawing of 1178 lines, arcs and shapes, not listed
  text "1" at 739.84,8036.5 h70
  text "2" at 3235.5,8036.5 h70
  text "3" at 5724.84,8036.5 h70
  text "4" at 8231.51,8036.5 h70
  text "5" at 10730.5,8036.5 h70
  text "6" at 13235.5,8036.5 h70
  text "A" at -416.5,6893.5 h70
  text "A" at 14383.5,6893.5 h70
  text "B" at -416.5,4513.5 h70
  text "B" at 14383.5,4513.5 h70
  text "C" at -416.5,2138.5 h70
  text "C" at 14383.5,2138.5 h70
  text "PROJECT TITLE:" at 11343.5,277.5 h45
  text ".PRJ_Title" at 11393.5,144.17 h70
  text "DESIGNED FOR:" at 11343.5,-23.5 h45
  text ".PRJ_Customer" at 11393.5,-163.5 h70
  text "D" at -416.5,-231.5 h70
  text "D" at 14383.5,-231.5 h70
  text "FILE NAME:" at 11343.5,-323.5 h45
  text ".PCB_File_Name_No_Path" at 11393.5,-443.5 h70
  text "Texas Instruments (TI) and/or its licensors do not warrant the accuracy or completeness of this specification" at 6374,-605.34 h45
  text "ENGINEER:" at 11343.5,-613.5 h45
  text "LAYOUT BY:" at 12848.5,-613.5 h45
  text "or any information contained therein. TI and/or its licensors do not warrant that this design will meet" at 6329.01,-718 h45
  text ".PRJ_Engineer" at 11393.5,-768.49 h70
  text "JMM" at 12856.28,-803.5 h100
  text "s  o  l  u  t  i  o  n  s" at 13714.28,-806.5 h68
  text "the specifications, will be suitable for your application or fit for any particular purpose, or will operate in" at 6329.01,-830.67 h45
  text ".Layer_Name" at 577,-858.49 h60
  text "ALTIUM DESIGNER VERSION:" at 12848.5,-923.5 h45
  text "an implementation. TI and/or its licensors do not warrant that the design is production worthy. You should" at 6329.01,-943.33 h45
  text "completely validate and test your design implementation to confirm the system functionality for your application." at 6374,-1056 h45
  text ".print_Scale" at 11393.5,-1056.83 h70
  text ".Application_BuildNumber" at 12899,-1056.83 h70
  text "1" at 739.84,-1263.5 h70
  text "2" at 3235.5,-1263.5 h70
  text "3" at 5724.84,-1263.5 h70
  text "4" at 8231.51,-1263.5 h70
  text "5" at 10730.5,-1263.5 h70
  text "6" at 13235.5,-1263.5 h70
M10 Fab Notes:
  drawing of 185 lines, arcs and shapes, not listed
  text "DESIGN INFORMATION" at 12381.02,5910 h60
  text "MIN. TRACK WIDTH:" at 11736.46,5730 h60
  text "5" at 12832.7,5730 h60
  text "MIL" at 12987.46,5730 h60
  text "4" at 12835,5600 h60
  text "MIN. CLEARANCE:" at 11736.46,5598 h60
  text "MIL" at 12987.46,5598 h60
  text "MIN. VIA PAD SIZE:" at 11736.46,5466 h60
  text "12" at 12802.71,5466 h60
  text "MIL" at 12987.46,5466 h60
  text "0.05mm (2MIL)" at 12431.46,5324.29 h60
  text "MINIMUM ANNULAR RING" at 11407.23,5320 h60
  text "EXTERNAL" at 13139.46,5320 h60
  text "PER" at 11607.23,5202 h60
  text "IPC-D-275 CLASS 2 LEVEL C" at 11827.23,5202 h60
  text "MIL, HOLES" at 13315.46,5089.71 h60
  text "+/-" at 12923,5089 h60
  text "+/-" at 13777,5089 h60
  text "REGISTRATION TOLERANCES:" at 11407.23,5084 h60
  text "METAL" at 12607,5084 h60
  text "5" at 13183.2,5084 h60
  text "3" at 14016.2,5084 h60
  text "MIL" at 14132.46,5084 h60
  text "Impedance Control:" at 7179,4883 h200
  text "MATERIAL:" at 11332.46,4874.54 h60
  text "FR-4 High Tg" at 12318.9,4734.21 h60
  text "FR-408" at 11753.46,4725.64 h60
  text "X" at 12165.46,4725.64 h60
  text "OTHER" at 13241.46,4725.64 h60
  text "Top Layer: 50 ohm impedance (+/- 10%) single ended for 9.5 mil traces." at 7178,4581 h125
  text "62 MIL (1.6mm) +/-10%" at 12073.56,4562.92 h60
  text "THICKNESS:" at 11407.23,4558.64 h60
  text "X" at 11945.4,4558.64 h60
  text "OTHER" at 13358.46,4558.64 h60
  text "TOLERANCE:" at 11407.23,4400.64 h60
  text "X" at 12246.53,4400.64 h60
  text "ANSI IPC-6012 TYPE 3 CLASS 2" at 12433.48,4400.64 h60
  text "Top Layer: 100 ohm impedance (+/-10%) for diff. pairs with" at 7178,4395 h125
  text "OTHER +/-" at 12433.46,4244.64 h60
  text "5 mil width and 5.5 mil spacing." at 7807,4244 h125
  text "BOW & TWIST:" at 11407.23,4087.64 h60
  text "X" at 12246.53,4087.64 h60
  text "ANSI IPC-6012 TYPE 3 CLASS 2" at 12433.48,4087.64 h60
  text "Layer 3: 50 ohm impedance (+/- 10%) single ended for 5.5 mil traces." at 7180,4080 h125
  text "OTHER +/-" at 12433.46,3929.13 h60
  text "DRILLING:" at 11332.46,3790.64 h60
  text "REFERENCE:" at 11407.23,3673.64 h60
  text "X" at 12055.46,3673.64 h60
  text "AS SHOWN" at 12242.46,3673.64 h60
  text "X" at 12956.46,3673.64 h60
  text "NC_DRILL FILES" at 13093.46,3673.64 h60
  text "PTH MIN COPPER THICKNESS:" at 11407.23,3515.64 h60
  text "X" at 12757.46,3515.64 h60
  text "1MIL" at 12894.46,3515.64 h60
  text "OTHER" at 13391.46,3515.64 h60
  text "BOARD FINISH:" at 11332.46,3356.64 h60
  text "SILKSCREEN:" at 11487.68,3238.64 h60
  text "X" at 12436.46,3238.64 h60
  text "TOP" at 12562.46,3238.64 h60
  text "X" at 12946.46,3238.64 h60
  text "BOTTOM" at 13073.46,3238.64 h60
  text "SILKSCREEN COLOR:" at 11487.68,3071.64 h60
  text "X" at 12435.42,3071.64 h60
  text "WHITE" at 12562.46,3071.64 h60
  text "OTHER" at 13073.46,3071.64 h60
  text "SOLDER RESIST COLOR:" at 11487.68,2901.64 h60
  text "X" at 13162,2746 h60
  text "GREEN" at 12182.46,2742.44 h60
  text "BLUE" at 12773.46,2742.44 h60
  text "OTHER" at 13311.46,2742.44 h60
  text "BLACK" at 13794,2740 h60
  text "IMMERSION GOLD (ENIG)" at 12393.46,2553.92 h60
  text "ENEPIG" at 13731,2550.64 h60
  text "SURFACE FINISH:" at 11332.46,2549.64 h60
  text "X" at 12206.51,2549.64 h60
  text "IMM. TIN/SILVER OR EQUIV" at 11662,2392.64 h60
  text "OTHER" at 13093.46,2392.64 h60
  text "ARRAY/PANEL:" at 11332.46,2213.64 h60
  text "CUT AND TRIM PER MECH LAYER 1" at 12393.46,2209.35 h60
  text "N.C. ROUTE" at 12393.46,2057.64 h60
  text "X" at 13072.46,2057.64 h60
  text "V. SCORE" at 13259.46,2057.64 h60
  text "CERTIFICATION:" at 11332.46,1920.64 h60
  text "MATERIALS AND WORKMANSHIP FOR ALL PCBS" at 12057.46,1920.64 h60
  text "TO MEET OR EXCEED THE REQUIREMENTS OF:" at 12057.46,1822.64 h60
  text "X" at 11683.96,1686.13 h60
  text "ANSI IPC-A-600F CLASS ->" at 11822.96,1686.13 h60
  text "X" at 13462.02,1686.13 h60
  text "2" at 13580.96,1686.14 h60
  text "1" at 13265.96,1684.64 h60
  text "3" at 13934.96,1684.64 h60
  text "X" at 11686.02,1526.64 h60
  text "UL 94V-0" at 11822.96,1526.64 h60
  text "X" at 12498.02,1526.64 h60
  text "RoHS" at 12634.96,1526.64 h60
  text "OTHER" at 13279.36,1526.64 h60
  text "PER ORDER" at 13676.42,1526.64 h60
  text "ADDITIONAL REQUIREMENTS:" at 11332.46,1385.64 h60
  text "MICROSECTION:" at 11407.23,1270.64 h60
  text "YES" at 12312.96,1270.64 h60
  text "REQUIRED" at 13174.46,1114.49 h60
  text "BARE BOARD ELEC. TEST:" at 11407.23,1111.64 h60
  text "NONE" at 12712.96,1111.64 h60
  text "X" at 13047.46,1111.64 h60
  text "PER ORDER" at 13766.46,1111.64 h60
  text "MANUFACTURER'S UL:" at 11407.23,954.64 h60
  text "RAIL" at 12572.96,950.35 h60
  text "METAL" at 13064.77,950.35 h60
  text "X" at 13440,950 h60
  text "SILK" at 13576.46,950.35 h60
  text ".Layer_Name" at 577,-858.49 h60
M11 Gerber Information:
  lines w10: -292,-930.17 6308,-930.17 ; -292,-726.83 6310,-726.83 ; -292,-523.5 -292,-1133.5 3713,-1133.5 6310,-1133.5 6310,-523.5 -291.5,-523.5 -291.5,-1133.5 1284,-1133.5 ; 2173,-1133.5 2173,-523.5 ; 3440,-726.83 3440,-523.5 ; 4280,-726.83 4280,-523.5 ; 4902,-1140 4902,-937.17
  text "ALL ARTWORK VIEWED FROM TOP SIDE" at -228.5,-655.67 h60
  text "BOARD #:" at 2248,-655.67 h60
  text ".PRJ_Number" at 2793.5,-655.67 h60
  text "REV:" at 3638,-655.67 h60
  text ".PCB_Rev" at 3929.5,-655.67 h60
  text "SVN REV:" at 4476,-655.67 h60
  text ".VersionControl_RevNumber" at 4982,-655.67 h60
  text "LAYER NAME =" at -228.5,-858.49 h60
  text "PLOT NAME =" at -228.5,-1064.34 h60
  text ".plot_File_Name" at 577,-1064.34 h60
  text "GENERATED    :" at 2250,-1064.34 h60
  text ".Print_Date" at 3119.5,-1064.34 h60
  text ".Print_Time" at 3848.5,-1064.34 h60
  text "TEXAS INSTRUMENTS" at 5113,-1064.34 h60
